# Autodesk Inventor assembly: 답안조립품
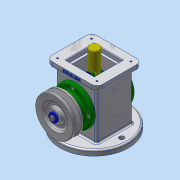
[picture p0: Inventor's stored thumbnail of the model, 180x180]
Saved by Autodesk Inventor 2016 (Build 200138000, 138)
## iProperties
Created: 2018-10
Part Number: 답안조립품
Document SubType Name: Assembly
Designer: MIRAE
Author: MIRAE
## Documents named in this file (17)
- C:\Users\MIRAE\Desktop\481007V1049\답안조립품.iam
- C:\Users\MIRAE\Desktop\481007V1049\본체.ipt
- C:\Users\MIRAE\Desktop\481007V1049\편심축.ipt
- C:\Users\MIRAE\Desktop\481007V1049\베어링 17 x 40 x 12.ipt
- C:\Users\MIRAE\Desktop\481007V1049\뒤커버.ipt
- C:\Users\MIRAE\Desktop\481007V1049\볼트 M4 x 8.ipt
- C:\Users\MIRAE\Desktop\481007V1049\앞커버.ipt
- C:\Users\MIRAE\Desktop\481007V1049\링크.ipt
- C:\Users\MIRAE\Desktop\481007V1049\클레비스 핀 6 x 22.ipt
- 클레비스 핀 6 x 22.ipt
- C:\Users\MIRAE\Desktop\481007V1049\슬라이더.ipt
- C:\Users\MIRAE\Desktop\481007V1049\E-링.ipt
- C:\Users\MIRAE\Desktop\481007V1049\키 4 x 4 x 12.ipt
- C:\Users\MIRAE\Desktop\481007V1049\오일 실 17 30 8.ipt
- C:\Users\MIRAE\Desktop\481007V1049\V-벨트풀리.ipt
- C:\Users\MIRAE\Desktop\481007V1049\와셔 4x16.ipt
- C:\Users\MIRAE\Desktop\481007V1049\볼트 M4 x 10.ipt
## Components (2 placed, 2 different names)
1. E-링:1
2. V-벨트풀리:1
